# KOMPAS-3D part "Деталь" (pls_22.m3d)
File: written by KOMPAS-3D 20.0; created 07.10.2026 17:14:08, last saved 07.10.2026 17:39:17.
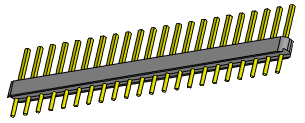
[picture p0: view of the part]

Document properties: Полное имя файла: D:\myProjects\Progect_esp32\box_compas\разъемы\pls_22.m3d

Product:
- Part/product: Деталь
    Масса: 0.00285166
  - Body: Тело 1
      Масса: 0.00286774

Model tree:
1. Эскиз:1
2. Элемент выдавливания:1
     Расстояние 1 = 2.5
3. Эскиз:2  (with: Элемент выдавливания:1)
4. Элемент выдавливания:2
     Расстояние 1 = 6
5. Массив по сетке:1  (with: Элемент выдавливания:2, Эскиз:2)  (22 pattern instances)
     Шаг 1 = 2.54; Угол раствора = 90
6. Эскиз:3  (with: Элемент выдавливания:1)
7. Элемент выдавливания:3
     Расстояние 1 = 3
8. Массив по сетке:2  (with: Элемент выдавливания:3, Эскиз:3)  (22 pattern instances)
     Шаг 1 = 2.54; Угол раствора = 90; Геометрический массив = 128
9. Эскиз:4  (with: Элемент выдавливания:1)
10. Элемент выдавливания:4
     Расстояние 2 = 55.88
11. Скругление:1  (with: Элемент выдавливания:1)
     Радиус = 1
